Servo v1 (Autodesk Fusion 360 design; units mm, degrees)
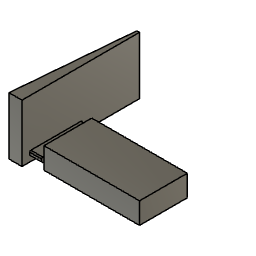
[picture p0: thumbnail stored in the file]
sketch "Sketch1" plane through (0, 0, 0) normal (0, 0, 1) x axis (1, 0, 0)
  line L1 (40, 0) -> (0, 0)
  line L2 (40, 20) -> (40, 0)
  line L3 (0, 20) -> (40, 20)
  line L4 (0, 0) -> (0, 20)
  point P1 (0, 0)
  point P2 (0, 0)
  horizontal L1
  vertical L2
  horizontal L3
  vertical L4
  coincident P1 P2
extrude "Extrude1" new body sketch "Sketch1" along normal blind 8.9
sketch "Sketch2" plane through (0, 0, 0) normal (1, 0, 0) x axis (0, 1, 0)
  line L1 (-1, 5) -> (21, 5)
  line L2 (-1, 3) -> (-1, 5)
  line L3 (21, 3) -> (-1, 3)
  line L4 (21, 5) -> (21, 3)
  horizontal L1
  vertical L2
  horizontal L3
  vertical L4
extrude "Extrude2" new body sketch "Sketch2" along normal blind 0 and against normal blind 5
cylinder_primitive "CylinderPrimitive1" Height -5 Diameter 1.78
fillet "Fillet1" radius 0.5
fillet "Fillet2" radius 0.5
fillet "Fillet3" radius 0.5
fillet "Fillet4" radius 0.5
sketch "Sketch4" plane through (0, 0, 0) normal (1, 0, 0) x axis (0, 1, 0)
  line L1 (-4.2128, 25) -> (45, 25)
  line L2 (-4.2128, 0.9481) -> (-4.2128, 25)
  line L3 (45, 0.9481) -> (-4.2128, 0.9481)
  line L4 (45, 25) -> (45, 0.9481)
  horizontal L1
  vertical L2
  horizontal L3
  vertical L4
extrude "Extrude3" add sketch "Sketch4" against normal blind 9 and against normal blind 5
move_face "MoveFace1"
